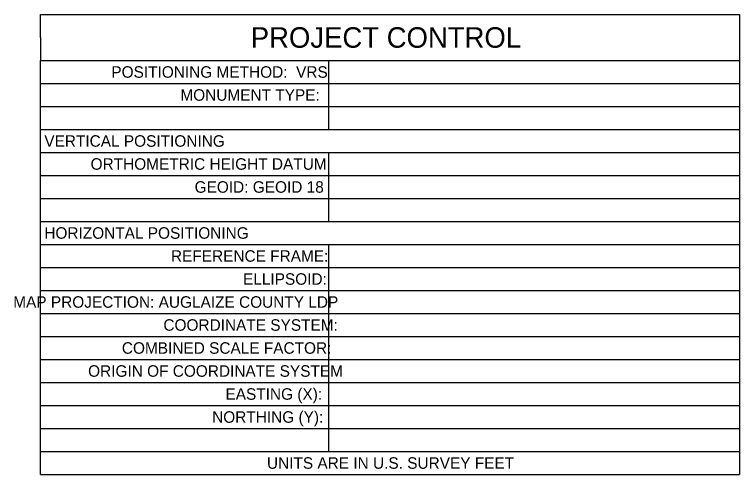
# Model space of a CAD drawing. Extents: x -11.1 to 34, y -3.9 to 22.
# Drawn here: x -11.06 to -2.25, y 7.75 to 13.35 of the extents above; entities that cross this region are included whole.
import ezdxf

# ---------------------------------------------------------------- set-up
doc = ezdxf.new("R2010")
doc.units = 0
doc.layers.add('PM_P_Cells', color=7, linetype='Continuous')
doc.layers.add('SH_Text', color=7, linetype='Continuous')

msp = doc.modelspace()

# ---------------------------------------------------------------- linework, layer by layer
at = {"layer": 'SH_Text'}
for p, q in [((-2.2465, 13.3479), (-2.2465, 13.0679)), ((-10.7465, 13.0679), (-10.7465, 12.7879)), ((-2.2465, 13.0679), (-2.2465, 12.7879)), ((-7.2465, 12.7879), (-2.2465, 12.7879)), ((-2.2465, 12.7879), (-2.2465, 12.5079)), ((-7.2465, 12.5079), (-2.2465, 12.5079)), ((-2.2465, 12.5079), (-2.2465, 12.2279)), ((-7.2465, 12.2279), (-2.2465, 12.2279)), ((-2.2465, 12.2279), (-2.2465, 11.9479)), ((-7.2465, 11.9479), (-2.2465, 11.9479)), ((-2.2465, 11.9479), (-2.2465, 11.6679)), ((-7.2465, 11.6679), (-2.2465, 11.6679)), ((-2.2465, 11.6679), (-2.2465, 11.3879)), ((-7.2465, 11.3879), (-2.2465, 11.3879)), ((-2.2465, 11.3879), (-2.2465, 11.1079)), ((-7.2465, 11.1079), (-2.2465, 11.1079)), ((-2.2465, 11.1079), (-2.2465, 10.8279)), ((-7.2465, 10.8279), (-2.2465, 10.8279)), ((-2.2465, 10.8279), (-2.2465, 10.5479)), ((-7.2465, 10.5479), (-2.2465, 10.5479)), ((-2.2465, 10.5479), (-2.2465, 10.2679)), ((-7.2465, 10.2679), (-2.2465, 10.2679)), ((-2.2465, 10.2679), (-2.2465, 9.9879)), ((-7.2465, 9.9879), (-2.2465, 9.9879)), ((-2.2465, 9.9879), (-2.2465, 9.7079)), ((-7.2465, 9.7079), (-2.2465, 9.7079)), ((-2.2465, 9.7079), (-2.2465, 9.4279)), ((-7.2465, 9.4279), (-2.2465, 9.4279)), ((-2.2465, 9.4279), (-2.2465, 9.1479)), ((-7.2465, 9.1479), (-2.2465, 9.1479)), ((-2.2465, 9.1479), (-2.2465, 8.8679)), ((-7.2465, 8.8679), (-2.2465, 8.8679)), ((-2.2465, 8.8679), (-2.2465, 8.5879)), ((-7.2465, 8.5879), (-2.2465, 8.5879)), ((-2.2465, 8.5879), (-2.2465, 8.3079)), ((-7.2465, 8.3079), (-2.2465, 8.3079)), ((-2.2465, 8.3079), (-2.2465, 8.0279)), ((-7.2465, 8.0279), (-2.2465, 8.0279)), ((-2.2465, 8.0279), (-2.2465, 7.7479)), ((-10.7465, 7.7479), (-2.2465, 7.7479))]:
    msp.add_line(p, q, dxfattribs=at)
for points in [[(-10.7465, 13.0679), (-10.7465, 13.3479), (-2.2465, 13.3479)], [(-10.7465, 12.5079), (-10.7465, 12.7879), (-7.2465, 12.7879), (-7.2465, 12.5079)], [(-10.7465, 12.2279), (-10.7465, 12.5079), (-7.2465, 12.5079), (-7.2465, 12.2279)], [(-10.7465, 11.9479), (-10.7465, 12.2279), (-7.2465, 12.2279), (-7.2465, 11.9479)], [(-10.7465, 11.6679), (-10.7465, 11.9479), (-7.2465, 11.9479)], [(-10.7465, 11.3879), (-10.7465, 11.6679), (-7.2465, 11.6679), (-7.2465, 11.3879)], [(-10.7465, 11.1079), (-10.7465, 11.3879), (-7.2465, 11.3879), (-7.2465, 11.1079)], [(-10.7465, 10.8279), (-10.7465, 11.1079), (-7.2465, 11.1079), (-7.2465, 10.8279)], [(-10.7465, 10.5479), (-10.7465, 10.8279), (-7.2465, 10.8279)], [(-10.7465, 10.2679), (-10.7465, 10.5479), (-7.2465, 10.5479), (-7.2465, 10.2679)], [(-10.7465, 9.9879), (-10.7465, 10.2679), (-7.2465, 10.2679), (-7.2465, 9.9879)], [(-10.7465, 9.7079), (-10.7465, 9.9879), (-7.2465, 9.9879), (-7.2465, 9.7079)], [(-10.7465, 9.4279), (-10.7465, 9.7079), (-7.2465, 9.7079), (-7.2465, 9.4279)], [(-10.7465, 9.1479), (-10.7465, 9.4279), (-7.2465, 9.4279), (-7.2465, 9.1479)], [(-10.7465, 8.8679), (-10.7465, 9.1479), (-7.2465, 9.1479), (-7.2465, 8.8679)], [(-10.7465, 8.5879), (-10.7465, 8.8679), (-7.2465, 8.8679), (-7.2465, 8.5879)], [(-10.7465, 8.3079), (-10.7465, 8.5879), (-7.2465, 8.5879), (-7.2465, 8.3079)], [(-10.7465, 8.0279), (-10.7465, 8.3079), (-7.2465, 8.3079), (-7.2465, 8.0279)], [(-10.7465, 7.7479), (-10.7465, 8.0279), (-7.2465, 8.0279)]]:
    msp.add_lwpolyline(points, dxfattribs=at)

# ---------------------------------------------------------------- texts
at = {"layer": 'PM_P_Cells'}
for s, height, p in [('PROJECT CONTROL', 0.25, (-8.1903, 12.9429)), ('POSITIONING METHOD:  VRS ', 0.14, (-9.8859, 12.5779)), ('MONUMENT TYPE:', 0.14, (-9.0466, 12.2979)), ('VERTICAL POSITIONING', 0.14, (-10.7013, 11.7379)), ('ORTHOMETRIC HEIGHT DATUM:', 0.14, (-10.1382, 11.4579)), ('GEOID: GEOID 18', 0.14, (-8.8733, 11.1779)), ('HORIZONTAL POSITIONING', 0.14, (-10.7013, 10.6179)), ('REFERENCE FRAME:', 0.14, (-9.1607, 10.3379)), ('ELLIPSOID:', 0.14, (-8.2846, 10.0579)), ('MAP PROJECTION: AUGLAIZE COUNTY LDP', 0.14, (-11.0791, 9.7779)), ('COORDINATE SYSTEM:', 0.14, (-9.253, 9.4979)), ('COMBINED SCALE FACTOR:', 0.14, (-9.758, 9.2179)), ('ORIGIN OF COORDINATE SYSTEM', 0.14, (-10.1688, 8.9379)), ('EASTING (X):', 0.14, (-8.498, 8.6579)), ('NORTHING (Y):', 0.14, (-8.6602, 8.3779)), ('UNITS ARE IN U.S. SURVEY FEET', 0.14, (-7.9935, 7.8179))]:
    msp.add_text(s, height=height, dxfattribs=at).set_placement(p)

doc.saveas('drawing.dxf')
